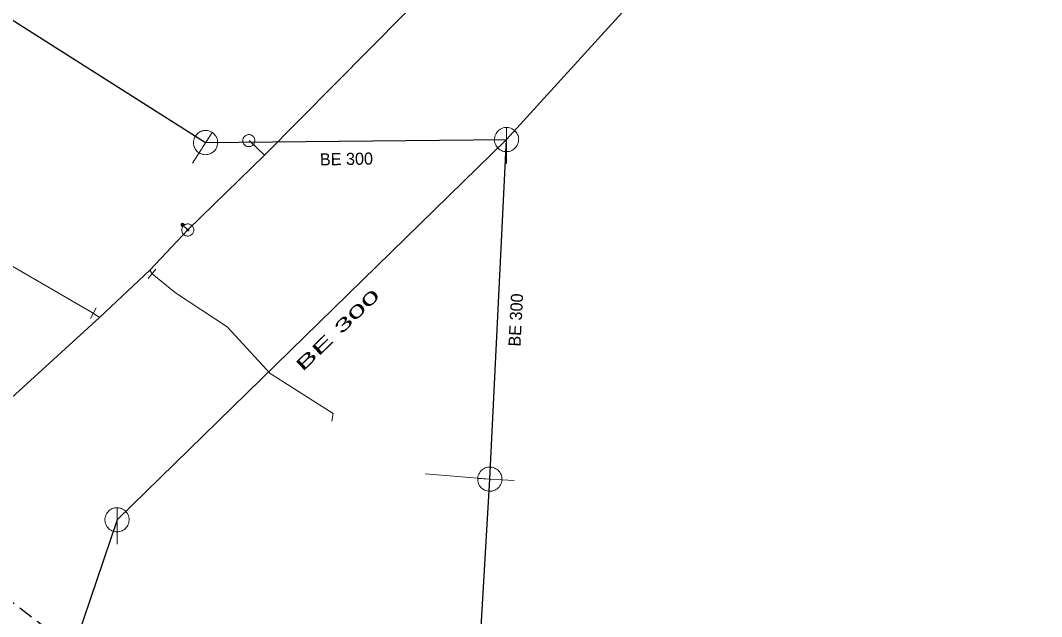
# Model space of a CAD drawing. Extents: x -791337 to -790755, y -988454 to -987923.
# Drawn here: x -791114.4 to -791030.1, y -988240 to -988190.7 of the extents above; entities that cross this region are included whole.
import ezdxf

# ---------------------------------------------------------------- set-up
doc = ezdxf.new("R2010")
doc.units = 0
doc.header["$LTSCALE"] = 0.4
doc.linetypes.add('MEDIUM_DASHED', pattern=[4.5, 3, -1.5])
for name, color, linetype, lineweight in [('1', 7, 'Continuous', 13), ('11', 7, 'Continuous', 13), ('13', 7, 'Continuous', 13), ('14', 7, 'Continuous', 25), ('17', 7, 'Continuous', 25), ('22', 7, 'Continuous', 13), ('23', 7, 'Continuous', 13), ('34', 7, 'Continuous', 13), ('47', 7, 'Continuous', 13), ('63', 7, 'MEDIUM_DASHED', 25), ('9', 7, 'Continuous', 13)]:
    doc.layers.add(name, color=color, linetype=linetype, lineweight=lineweight)

msp = doc.modelspace()

# ---------------------------------------------------------------- linework, layer by layer
at = {"layer": '11'}
msp.add_line((-791080.986, -988228.19), (-791075.638, -988228.634), dxfattribs=at)
at = {"layer": '13'}
for points in [[(-791107.868, -988215.265), (-791108.388, -988214.918), (-791149.015, -988191.33)], [(-791103.529, -988211.659), (-791101.609, -988213.23), (-791097.34, -988216.039), (-791093.789, -988219.899), (-791088.568, -988223.201), (-791088.693, -988223.848)]]:
    msp.add_lwpolyline(points, dxfattribs=at)
at = {"layer": '14'}
for p, q in [((-791137.55, -988176.404), (-791099.119, -988200.823)), ((-791106.431, -988231.991), (-791074.254, -988200.572)), ((-791099.119, -988200.823), (-791074.254, -988200.572)), ((-791106.431, -988231.991), (-791121.225, -988275.947))]:
    msp.add_line(p, q, dxfattribs=at)
at = {"layer": '14', "lineweight": 13}
for p, q in [((-791094.248, -988201.857), (-791095.51, -988200.659)), ((-791100.587, -988208.045), (-791101.018, -988207.619)), ((-791103.719, -988211.362), (-791103.529, -988211.659))]:
    msp.add_line(p, q, dxfattribs=at)
at = {"layer": '14'}
msp.add_lwpolyline([(-791078.328, -988268.275), (-791076.412, -988241.781), (-791075.638, -988228.634), (-791074.254, -988200.572), (-791046.212, -988169.71)], dxfattribs=at)
at = {"layer": '17'}
for points in [[(-791100.587, -988208.045), (-791094.248, -988201.857), (-791082.624, -988190.124), (-791067.283, -988176.118), (-791058.988, -988167.736)], [(-791134.081, -988239.197), (-791107.868, -988215.265), (-791103.719, -988211.362), (-791100.587, -988208.045)]]:
    msp.add_lwpolyline(points, dxfattribs=at)
at = {"layer": '22'}
for p, q in [((-791100.191, -988202.511), (-791098.582, -988199.979)), ((-791074.254, -988202.572), (-791074.253, -988199.572)), ((-791073.639, -988228.732), (-791076.636, -988228.584)), ((-791106.431, -988233.992), (-791106.43, -988230.992))]:
    msp.add_line(p, q, dxfattribs=at)
for points in [[(-791098.275, -988201.359), (-791098.221, -988201.264), (-791098.179, -988201.163), (-791098.147, -988201.058), (-791098.127, -988200.951), (-791098.119, -988200.841), (-791098.123, -988200.732), (-791098.139, -988200.623), (-791098.167, -988200.518), (-791098.206, -988200.415), (-791098.255, -988200.318), (-791098.316, -988200.227), (-791098.387, -988200.142), (-791098.465, -988200.066), (-791098.552, -988200), (-791098.646, -988199.942), (-791098.744, -988199.896), (-791098.848, -988199.86), (-791098.955, -988199.836), (-791099.064, -988199.825), (-791099.173, -988199.824), (-791099.282, -988199.836), (-791099.388, -988199.86), (-791099.493, -988199.896), (-791099.592, -988199.942), (-791099.685, -988199.999), (-791099.772, -988200.066), (-791099.851, -988200.142), (-791099.921, -988200.226), (-791099.981, -988200.318), (-791100.031, -988200.415), (-791100.071, -988200.516), (-791100.098, -988200.622), (-791100.115, -988200.73), (-791100.119, -988200.84), (-791100.111, -988200.95), (-791100.091, -988201.057), (-791100.06, -988201.162), (-791100.017, -988201.263), (-791099.964, -988201.358), (-791099.9, -988201.448), (-791099.827, -988201.529), (-791099.746, -988201.602), (-791099.656, -988201.666), (-791099.561, -988201.72), (-791099.46, -988201.763), (-791099.356, -988201.794), (-791099.248, -988201.814), (-791099.138, -988201.823), (-791099.029, -988201.819), (-791098.921, -988201.803), (-791098.814, -988201.776), (-791098.712, -988201.736), (-791098.615, -988201.687), (-791098.524, -988201.626), (-791098.439, -988201.557), (-791098.363, -988201.477), (-791098.296, -988201.391)], [(-791073.254, -988200.572), (-791073.259, -988200.463), (-791073.277, -988200.355), (-791073.307, -988200.249), (-791073.347, -988200.148), (-791073.399, -988200.051), (-791073.461, -988199.961), (-791073.533, -988199.878), (-791073.613, -988199.804), (-791073.701, -988199.738), (-791073.795, -988199.683), (-791073.895, -988199.638), (-791074, -988199.605), (-791074.107, -988199.583), (-791074.216, -988199.573), (-791074.326, -988199.575), (-791074.434, -988199.589), (-791074.541, -988199.614), (-791074.644, -988199.651), (-791074.742, -988199.7), (-791074.834, -988199.758), (-791074.92, -988199.827), (-791074.997, -988199.904), (-791075.066, -988199.99), (-791075.125, -988200.082), (-791075.173, -988200.18), (-791075.21, -988200.283), (-791075.236, -988200.39), (-791075.25, -988200.498), (-791075.253, -988200.608), (-791075.243, -988200.717), (-791075.222, -988200.824), (-791075.188, -988200.928), (-791075.144, -988201.028), (-791075.089, -988201.123), (-791075.023, -988201.211), (-791074.949, -988201.291), (-791074.866, -988201.363), (-791074.776, -988201.425), (-791074.68, -988201.477), (-791074.578, -988201.518), (-791074.473, -988201.548), (-791074.365, -988201.566), (-791074.255, -988201.572), (-791074.146, -988201.566), (-791074.038, -988201.548), (-791073.933, -988201.519), (-791073.831, -988201.478), (-791073.734, -988201.426), (-791073.644, -988201.364), (-791073.561, -988201.293), (-791073.486, -988201.213), (-791073.421, -988201.125), (-791073.365, -988201.031), (-791073.321, -988200.931), (-791073.287, -988200.827), (-791073.265, -988200.719), (-791073.255, -988200.61)], [(-791075.588, -988227.635), (-791075.697, -988227.635), (-791075.806, -988227.648), (-791075.913, -988227.673), (-791076.016, -988227.708), (-791076.115, -988227.755), (-791076.208, -988227.812), (-791076.295, -988227.88), (-791076.373, -988227.956), (-791076.443, -988228.041), (-791076.502, -988228.132), (-791076.552, -988228.23), (-791076.59, -988228.333), (-791076.618, -988228.439), (-791076.633, -988228.547), (-791076.636, -988228.657), (-791076.628, -988228.766), (-791076.608, -988228.874), (-791076.576, -988228.979), (-791076.532, -988229.079), (-791076.479, -988229.174), (-791076.414, -988229.263), (-791076.341, -988229.344), (-791076.258, -988229.417), (-791076.169, -988229.48), (-791076.074, -988229.533), (-791075.973, -988229.575), (-791075.867, -988229.606), (-791075.76, -988229.626), (-791075.65, -988229.633), (-791075.541, -988229.628), (-791075.433, -988229.613), (-791075.327, -988229.584), (-791075.225, -988229.545), (-791075.128, -988229.495), (-791075.037, -988229.433), (-791074.953, -988229.363), (-791074.877, -988229.284), (-791074.811, -988229.197), (-791074.754, -988229.104), (-791074.708, -988229.004), (-791074.673, -988228.9), (-791074.65, -988228.793), (-791074.638, -988228.684), (-791074.639, -988228.575), (-791074.652, -988228.466), (-791074.675, -988228.36), (-791074.711, -988228.256), (-791074.758, -988228.156), (-791074.816, -988228.063), (-791074.883, -988227.977), (-791074.959, -988227.898), (-791075.044, -988227.829), (-791075.135, -988227.768), (-791075.232, -988227.719), (-791075.335, -988227.68), (-791075.441, -988227.653), (-791075.55, -988227.638)], [(-791105.431, -988231.992), (-791105.436, -988231.883), (-791105.454, -988231.775), (-791105.484, -988231.669), (-791105.524, -988231.568), (-791105.576, -988231.471), (-791105.638, -988231.381), (-791105.71, -988231.298), (-791105.79, -988231.224), (-791105.878, -988231.158), (-791105.972, -988231.103), (-791106.072, -988231.058), (-791106.177, -988231.025), (-791106.284, -988231.003), (-791106.393, -988230.993), (-791106.503, -988230.995), (-791106.611, -988231.009), (-791106.718, -988231.034), (-791106.821, -988231.071), (-791106.919, -988231.12), (-791107.011, -988231.178), (-791107.097, -988231.247), (-791107.174, -988231.324), (-791107.243, -988231.41), (-791107.302, -988231.502), (-791107.35, -988231.6), (-791107.387, -988231.703), (-791107.413, -988231.81), (-791107.427, -988231.918), (-791107.43, -988232.028), (-791107.42, -988232.137), (-791107.399, -988232.244), (-791107.365, -988232.348), (-791107.321, -988232.448), (-791107.266, -988232.543), (-791107.2, -988232.631), (-791107.126, -988232.711), (-791107.043, -988232.783), (-791106.953, -988232.845), (-791106.857, -988232.897), (-791106.755, -988232.938), (-791106.65, -988232.968), (-791106.542, -988232.986), (-791106.432, -988232.992), (-791106.323, -988232.986), (-791106.215, -988232.968), (-791106.11, -988232.939), (-791106.008, -988232.898), (-791105.911, -988232.846), (-791105.821, -988232.784), (-791105.738, -988232.713), (-791105.663, -988232.633), (-791105.598, -988232.545), (-791105.542, -988232.451), (-791105.498, -988232.351), (-791105.464, -988232.247), (-791105.442, -988232.139), (-791105.432, -988232.03)]]:
    msp.add_lwpolyline(points, close=True, dxfattribs=at)
at = {"layer": '23'}
for points in [[(-791095.175, -988200.999), (-791095.141, -988200.959), (-791095.112, -988200.915), (-791095.089, -988200.869), (-791095.069, -988200.821), (-791095.055, -988200.771), (-791095.046, -988200.718), (-791095.043, -988200.666), (-791095.045, -988200.615), (-791095.052, -988200.563), (-791095.065, -988200.512), (-791095.082, -988200.462), (-791095.106, -988200.415), (-791095.133, -988200.371), (-791095.166, -988200.331), (-791095.201, -988200.293), (-791095.243, -988200.259), (-791095.285, -988200.23), (-791095.333, -988200.205), (-791095.379, -988200.186), (-791095.43, -988200.171), (-791095.483, -988200.163), (-791095.535, -988200.159), (-791095.588, -988200.162), (-791095.64, -988200.168), (-791095.689, -988200.181), (-791095.739, -988200.2), (-791095.785, -988200.223), (-791095.83, -988200.251), (-791095.871, -988200.284), (-791095.909, -988200.319), (-791095.942, -988200.359), (-791095.971, -988200.403), (-791095.996, -988200.45), (-791096.016, -988200.498), (-791096.028, -988200.547), (-791096.038, -988200.599), (-791096.042, -988200.652), (-791096.04, -988200.705), (-791096.032, -988200.756)], [(-791095.333, -988200.205), (-791095.379, -988200.186), (-791095.43, -988200.171), (-791095.483, -988200.163), (-791095.535, -988200.159), (-791095.588, -988200.162), (-791095.64, -988200.168), (-791095.689, -988200.181), (-791095.739, -988200.2), (-791095.785, -988200.223), (-791095.83, -988200.251), (-791095.871, -988200.284), (-791095.909, -988200.319), (-791095.942, -988200.359), (-791095.971, -988200.403), (-791095.996, -988200.45), (-791096.016, -988200.498), (-791096.028, -988200.547), (-791096.038, -988200.599), (-791096.042, -988200.652), (-791096.04, -988200.705), (-791096.032, -988200.756), (-791096.02, -988200.806), (-791096.001, -988200.856), (-791095.979, -988200.903), (-791095.95, -988200.947), (-791095.918, -988200.987), (-791095.882, -988201.025), (-791095.842, -988201.058), (-791095.798, -988201.088), (-791095.752, -988201.113), (-791095.703, -988201.132), (-791095.653, -988201.146), (-791095.602, -988201.156), (-791095.549, -988201.158), (-791095.497, -988201.157), (-791095.446, -988201.149), (-791095.394, -988201.137), (-791095.345, -988201.119), (-791095.298, -988201.095)], [(-791096.032, -988200.756), (-791096.02, -988200.806), (-791096.001, -988200.856), (-791095.979, -988200.903), (-791095.95, -988200.947), (-791095.918, -988200.987), (-791095.882, -988201.025), (-791095.842, -988201.058), (-791095.798, -988201.088), (-791095.752, -988201.113), (-791095.703, -988201.132), (-791095.653, -988201.146), (-791095.602, -988201.156), (-791095.549, -988201.158), (-791095.497, -988201.157), (-791095.446, -988201.149), (-791095.394, -988201.137), (-791095.345, -988201.119), (-791095.298, -988201.095), (-791095.254, -988201.067), (-791095.213, -988201.035), (-791095.175, -988200.999), (-791095.141, -988200.959), (-791095.112, -988200.915), (-791095.089, -988200.869), (-791095.069, -988200.821), (-791095.055, -988200.771), (-791095.046, -988200.718), (-791095.043, -988200.666), (-791095.045, -988200.615), (-791095.052, -988200.563), (-791095.065, -988200.512), (-791095.082, -988200.462), (-791095.106, -988200.415), (-791095.133, -988200.371), (-791095.166, -988200.331), (-791095.201, -988200.293), (-791095.243, -988200.259), (-791095.285, -988200.23), (-791095.333, -988200.205)], [(-791095.298, -988201.095), (-791095.254, -988201.067), (-791095.213, -988201.035), (-791095.175, -988200.999)]]:
    msp.add_lwpolyline(points, dxfattribs=at)
at = {"layer": '34'}
for p, q in [((-791103.212, -988211.271), (-791103.845, -988212.045)), ((-791108.14, -988214.483), (-791108.635, -988215.352))]:
    msp.add_line(p, q, dxfattribs=at)
at = {"layer": '47'}
for points in [[(-791100.087, -988208.045), (-791100.09, -988207.993), (-791100.098, -988207.941), (-791100.112, -988207.891), (-791100.13, -988207.842), (-791100.154, -988207.795), (-791100.183, -988207.751), (-791100.216, -988207.711), (-791100.253, -988207.674), (-791100.293, -988207.641), (-791100.337, -988207.612), (-791100.384, -988207.588), (-791100.433, -988207.57), (-791100.483, -988207.556), (-791100.535, -988207.548), (-791100.587, -988207.545), (-791100.639, -988207.548), (-791100.691, -988207.556), (-791100.742, -988207.57), (-791100.79, -988207.588), (-791100.837, -988207.612), (-791100.881, -988207.641), (-791100.922, -988207.674), (-791100.959, -988207.711), (-791100.992, -988207.751), (-791101.02, -988207.795), (-791101.044, -988207.842), (-791101.063, -988207.891), (-791101.076, -988207.941), (-791101.084, -988207.993), (-791101.087, -988208.045), (-791101.084, -988208.097), (-791101.076, -988208.149), (-791101.063, -988208.2), (-791101.044, -988208.248), (-791101.02, -988208.295), (-791100.992, -988208.339), (-791100.959, -988208.38), (-791100.922, -988208.417), (-791100.881, -988208.45), (-791100.837, -988208.478), (-791100.79, -988208.502), (-791100.742, -988208.521), (-791100.691, -988208.534), (-791100.639, -988208.542), (-791100.587, -988208.545), (-791100.535, -988208.542), (-791100.483, -988208.534), (-791100.433, -988208.521), (-791100.384, -988208.502), (-791100.337, -988208.478), (-791100.293, -988208.45), (-791100.253, -988208.417), (-791100.216, -988208.38), (-791100.183, -988208.339), (-791100.154, -988208.295), (-791100.13, -988208.248), (-791100.112, -988208.2), (-791100.098, -988208.149), (-791100.09, -988208.097)], [(-791100.505, -988208.045), (-791100.505, -988208.036), (-791100.507, -988208.028), (-791100.509, -988208.02), (-791100.512, -988208.012), (-791100.516, -988208.004), (-791100.521, -988207.997), (-791100.526, -988207.99), (-791100.532, -988207.984), (-791100.539, -988207.979), (-791100.546, -988207.974), (-791100.554, -988207.97), (-791100.562, -988207.967), (-791100.57, -988207.965), (-791100.578, -988207.963), (-791100.587, -988207.963), (-791100.596, -988207.963), (-791100.604, -988207.965), (-791100.612, -988207.967), (-791100.62, -988207.97), (-791100.628, -988207.974), (-791100.635, -988207.979), (-791100.642, -988207.984), (-791100.648, -988207.99), (-791100.654, -988207.997), (-791100.658, -988208.004), (-791100.662, -988208.012), (-791100.665, -988208.02), (-791100.667, -988208.028), (-791100.669, -988208.036), (-791100.669, -988208.045), (-791100.669, -988208.054), (-791100.667, -988208.062), (-791100.665, -988208.07), (-791100.662, -988208.078), (-791100.658, -988208.086), (-791100.654, -988208.093), (-791100.648, -988208.1), (-791100.642, -988208.106), (-791100.635, -988208.112), (-791100.628, -988208.116), (-791100.62, -988208.12), (-791100.612, -988208.123), (-791100.604, -988208.125), (-791100.596, -988208.127), (-791100.587, -988208.127), (-791100.578, -988208.127), (-791100.57, -988208.125), (-791100.562, -988208.123), (-791100.554, -988208.12), (-791100.546, -988208.116), (-791100.539, -988208.112), (-791100.532, -988208.106), (-791100.526, -988208.1), (-791100.521, -988208.093), (-791100.516, -988208.086), (-791100.512, -988208.078), (-791100.509, -988208.07), (-791100.507, -988208.062), (-791100.505, -988208.054)]]:
    msp.add_lwpolyline(points, close=True, dxfattribs=at)
at = {"layer": '63'}
msp.add_lwpolyline([(-791231.02, -987923.132), (-790755.118, -988202.253), (-790755.118, -988202.253), (-790903.053, -988400.429), (-790903.053, -988400.429), (-791331.504, -988073.857), (-791331.504, -988073.857)], close=True, dxfattribs=at)
at = {"layer": '9'}
for points in [[(-791101.144, -988207.619), (-791101.144, -988207.632), (-791101.142, -988207.645), (-791101.139, -988207.658), (-791101.134, -988207.67), (-791101.128, -988207.682), (-791101.121, -988207.693), (-791101.113, -988207.703), (-791101.103, -988207.713), (-791101.093, -988207.721), (-791101.082, -988207.728), (-791101.07, -988207.734), (-791101.058, -988207.739), (-791101.045, -988207.742), (-791101.032, -988207.744), (-791101.019, -988207.746), (-791101.006, -988207.745), (-791100.993, -988207.743), (-791100.98, -988207.74), (-791100.968, -988207.735), (-791100.956, -988207.729), (-791100.945, -988207.722), (-791100.935, -988207.714), (-791100.925, -988207.704), (-791100.917, -988207.694), (-791100.91, -988207.683), (-791100.904, -988207.671), (-791100.899, -988207.659), (-791100.896, -988207.646), (-791100.894, -988207.633), (-791100.892, -988207.62), (-791100.893, -988207.607), (-791100.895, -988207.594), (-791100.898, -988207.581), (-791100.903, -988207.569), (-791100.909, -988207.557), (-791100.916, -988207.546), (-791100.924, -988207.536), (-791100.934, -988207.526), (-791100.944, -988207.518), (-791100.955, -988207.511), (-791100.967, -988207.505), (-791100.979, -988207.5), (-791100.992, -988207.497), (-791101.005, -988207.495), (-791101.018, -988207.494), (-791101.031, -988207.494), (-791101.044, -988207.496), (-791101.057, -988207.499), (-791101.069, -988207.504), (-791101.081, -988207.51), (-791101.092, -988207.517), (-791101.102, -988207.525), (-791101.112, -988207.535), (-791101.12, -988207.545), (-791101.127, -988207.556), (-791101.133, -988207.568), (-791101.138, -988207.58), (-791101.141, -988207.593), (-791101.143, -988207.606)], [(-791101.124, -988207.619), (-791101.125, -988207.63), (-791101.123, -988207.641), (-791101.12, -988207.652), (-791101.116, -988207.662), (-791101.111, -988207.672), (-791101.105, -988207.681), (-791101.098, -988207.69), (-791101.09, -988207.698), (-791101.081, -988207.705), (-791101.072, -988207.711), (-791101.062, -988207.716), (-791101.052, -988207.72), (-791101.041, -988207.723), (-791101.03, -988207.726), (-791101.019, -988207.726), (-791101.008, -988207.726), (-791100.997, -988207.724), (-791100.986, -988207.721), (-791100.976, -988207.717), (-791100.966, -988207.712), (-791100.957, -988207.706), (-791100.948, -988207.699), (-791100.94, -988207.691), (-791100.933, -988207.682), (-791100.927, -988207.673), (-791100.922, -988207.663), (-791100.918, -988207.653), (-791100.915, -988207.642), (-791100.913, -988207.631), (-791100.912, -988207.62), (-791100.912, -988207.609), (-791100.914, -988207.598), (-791100.917, -988207.587), (-791100.921, -988207.577), (-791100.926, -988207.567), (-791100.932, -988207.558), (-791100.939, -988207.549), (-791100.947, -988207.541), (-791100.956, -988207.534), (-791100.965, -988207.528), (-791100.975, -988207.523), (-791100.985, -988207.519), (-791100.996, -988207.516), (-791101.007, -988207.514), (-791101.018, -988207.514), (-791101.029, -988207.513), (-791101.04, -988207.515), (-791101.051, -988207.518), (-791101.061, -988207.522), (-791101.071, -988207.527), (-791101.08, -988207.533), (-791101.089, -988207.54), (-791101.097, -988207.548), (-791101.104, -988207.557), (-791101.11, -988207.566), (-791101.115, -988207.576), (-791101.119, -988207.586), (-791101.122, -988207.597), (-791101.124, -988207.608)], [(-791101.105, -988207.619), (-791101.105, -988207.628), (-791101.104, -988207.637), (-791101.101, -988207.646), (-791101.098, -988207.654), (-791101.094, -988207.662), (-791101.089, -988207.67), (-791101.083, -988207.677), (-791101.077, -988207.683), (-791101.07, -988207.689), (-791101.062, -988207.694), (-791101.054, -988207.698), (-791101.046, -988207.701), (-791101.037, -988207.704), (-791101.028, -988207.705), (-791101.019, -988207.707), (-791101.01, -988207.706), (-791101.001, -988207.705), (-791100.992, -988207.702), (-791100.984, -988207.699), (-791100.976, -988207.695), (-791100.968, -988207.69), (-791100.961, -988207.684), (-791100.955, -988207.678), (-791100.949, -988207.671), (-791100.944, -988207.663), (-791100.94, -988207.655), (-791100.937, -988207.647), (-791100.934, -988207.638), (-791100.933, -988207.629), (-791100.931, -988207.62), (-791100.932, -988207.611), (-791100.933, -988207.602), (-791100.936, -988207.593), (-791100.939, -988207.585), (-791100.943, -988207.577), (-791100.948, -988207.569), (-791100.954, -988207.562), (-791100.96, -988207.556), (-791100.967, -988207.55), (-791100.975, -988207.545), (-791100.983, -988207.541), (-791100.991, -988207.538), (-791101, -988207.535), (-791101.009, -988207.534), (-791101.018, -988207.533), (-791101.027, -988207.533), (-791101.036, -988207.534), (-791101.045, -988207.537), (-791101.053, -988207.54), (-791101.061, -988207.544), (-791101.069, -988207.549), (-791101.076, -988207.555), (-791101.082, -988207.561), (-791101.088, -988207.568), (-791101.093, -988207.576), (-791101.097, -988207.584), (-791101.1, -988207.592), (-791101.103, -988207.601), (-791101.104, -988207.61)], [(-791101.085, -988207.619), (-791101.085, -988207.626), (-791101.084, -988207.633), (-791101.083, -988207.64), (-791101.08, -988207.646), (-791101.077, -988207.652), (-791101.073, -988207.658), (-791101.069, -988207.664), (-791101.064, -988207.669), (-791101.058, -988207.673), (-791101.052, -988207.677), (-791101.046, -988207.68), (-791101.04, -988207.683), (-791101.033, -988207.684), (-791101.026, -988207.687), (-791101.019, -988207.687), (-791101.012, -988207.687), (-791101.005, -988207.685), (-791100.998, -988207.684), (-791100.992, -988207.681), (-791100.985, -988207.678), (-791100.98, -988207.674), (-791100.974, -988207.67), (-791100.969, -988207.665), (-791100.965, -988207.659), (-791100.961, -988207.653), (-791100.958, -988207.647), (-791100.955, -988207.641), (-791100.953, -988207.634), (-791100.952, -988207.627), (-791100.951, -988207.62), (-791100.951, -988207.613), (-791100.952, -988207.606), (-791100.954, -988207.599), (-791100.957, -988207.593), (-791100.96, -988207.586), (-791100.964, -988207.581), (-791100.968, -988207.575), (-791100.973, -988207.57), (-791100.979, -988207.566), (-791100.984, -988207.562), (-791100.991, -988207.559), (-791100.997, -988207.556), (-791101.004, -988207.554), (-791101.011, -988207.553), (-791101.018, -988207.553), (-791101.025, -988207.553), (-791101.032, -988207.553), (-791101.039, -988207.555), (-791101.045, -988207.558), (-791101.051, -988207.561), (-791101.057, -988207.565), (-791101.063, -988207.569), (-791101.068, -988207.574), (-791101.072, -988207.58), (-791101.076, -988207.585), (-791101.079, -988207.592), (-791101.082, -988207.598), (-791101.083, -988207.605), (-791101.085, -988207.612)], [(-791101.065, -988207.619), (-791101.065, -988207.624), (-791101.065, -988207.629), (-791101.064, -988207.634), (-791101.062, -988207.638), (-791101.06, -988207.643), (-791101.057, -988207.647), (-791101.054, -988207.65), (-791101.05, -988207.654), (-791101.047, -988207.657), (-791101.043, -988207.66), (-791101.038, -988207.662), (-791101.034, -988207.664), (-791101.029, -988207.665), (-791101.024, -988207.667), (-791101.019, -988207.667), (-791101.014, -988207.667), (-791101.009, -988207.666), (-791101.004, -988207.665), (-791101, -988207.663), (-791100.995, -988207.661), (-791100.991, -988207.658), (-791100.987, -988207.655), (-791100.984, -988207.651), (-791100.981, -988207.648), (-791100.978, -988207.644), (-791100.976, -988207.639), (-791100.974, -988207.635), (-791100.973, -988207.63), (-791100.972, -988207.625), (-791100.971, -988207.62), (-791100.971, -988207.615), (-791100.972, -988207.61), (-791100.973, -988207.605), (-791100.975, -988207.601), (-791100.977, -988207.596), (-791100.98, -988207.592), (-791100.983, -988207.588), (-791100.986, -988207.585), (-791100.99, -988207.582), (-791100.994, -988207.579), (-791100.999, -988207.577), (-791101.003, -988207.575), (-791101.008, -988207.574), (-791101.013, -988207.573), (-791101.018, -988207.573), (-791101.023, -988207.573), (-791101.028, -988207.574), (-791101.033, -988207.574), (-791101.037, -988207.576), (-791101.042, -988207.578), (-791101.046, -988207.581), (-791101.049, -988207.584), (-791101.053, -988207.587), (-791101.056, -988207.591), (-791101.059, -988207.595), (-791101.061, -988207.6), (-791101.063, -988207.604), (-791101.064, -988207.609), (-791101.065, -988207.614)], [(-791101.045, -988207.619), (-791101.045, -988207.622), (-791101.046, -988207.625), (-791101.045, -988207.627), (-791101.044, -988207.63), (-791101.043, -988207.633), (-791101.041, -988207.635), (-791101.039, -988207.637), (-791101.037, -988207.639), (-791101.035, -988207.641), (-791101.033, -988207.643), (-791101.03, -988207.645), (-791101.027, -988207.646), (-791101.025, -988207.646), (-791101.022, -988207.647), (-791101.019, -988207.647), (-791101.016, -988207.647), (-791101.013, -988207.647), (-791101.01, -988207.646), (-791101.008, -988207.645), (-791101.005, -988207.644), (-791101.003, -988207.642), (-791101, -988207.64), (-791100.998, -988207.638), (-791100.997, -988207.636), (-791100.995, -988207.634), (-791100.994, -988207.631), (-791100.992, -988207.628), (-791100.992, -988207.626), (-791100.991, -988207.623), (-791100.99, -988207.62), (-791100.991, -988207.617), (-791100.991, -988207.614), (-791100.992, -988207.611), (-791100.993, -988207.609), (-791100.994, -988207.606), (-791100.996, -988207.604), (-791100.997, -988207.601), (-791100.999, -988207.599), (-791101.002, -988207.598), (-791101.004, -988207.596), (-791101.007, -988207.595), (-791101.009, -988207.594), (-791101.012, -988207.593), (-791101.015, -988207.593), (-791101.018, -988207.592), (-791101.021, -988207.593), (-791101.024, -988207.592), (-791101.026, -988207.594), (-791101.029, -988207.594), (-791101.032, -988207.595), (-791101.034, -988207.597), (-791101.036, -988207.598), (-791101.038, -988207.6), (-791101.04, -988207.603), (-791101.042, -988207.605), (-791101.043, -988207.608), (-791101.044, -988207.61), (-791101.045, -988207.613), (-791101.045, -988207.616)], [(-791101.026, -988207.619), (-791101.026, -988207.621), (-791101.026, -988207.621), (-791101.025, -988207.621), (-791101.025, -988207.623), (-791101.026, -988207.624), (-791101.024, -988207.624), (-791101.024, -988207.624), (-791101.024, -988207.626), (-791101.024, -988207.626), (-791101.023, -988207.627), (-791101.021, -988207.627), (-791101.021, -988207.627), (-791101.021, -988207.628), (-791101.019, -988207.628), (-791101.019, -988207.628), (-791101.018, -988207.628), (-791101.017, -988207.628), (-791101.017, -988207.627), (-791101.016, -988207.627), (-791101.014, -988207.627), (-791101.014, -988207.626), (-791101.014, -988207.626), (-791101.013, -988207.625), (-791101.013, -988207.625), (-791101.011, -988207.624), (-791101.011, -988207.623), (-791101.01, -988207.622), (-791101.01, -988207.622), (-791101.01, -988207.621), (-791101.01, -988207.62), (-791101.01, -988207.619), (-791101.01, -988207.618), (-791101.01, -988207.618), (-791101.011, -988207.617), (-791101.011, -988207.616), (-791101.012, -988207.615), (-791101.012, -988207.615), (-791101.013, -988207.614), (-791101.013, -988207.614), (-791101.014, -988207.613), (-791101.015, -988207.613), (-791101.016, -988207.612), (-791101.016, -988207.612), (-791101.017, -988207.612), (-791101.018, -988207.612), (-791101.019, -988207.612), (-791101.02, -988207.612), (-791101.02, -988207.612), (-791101.021, -988207.613), (-791101.022, -988207.612), (-791101.023, -988207.614), (-791101.023, -988207.614), (-791101.024, -988207.614), (-791101.024, -988207.614), (-791101.025, -988207.616), (-791101.025, -988207.617), (-791101.025, -988207.618), (-791101.026, -988207.618), (-791101.026, -988207.619)]]:
    msp.add_lwpolyline(points, close=True, dxfattribs=at)

# ---------------------------------------------------------------- texts
at = {"layer": '1'}
for rotation, p in [(1, (-791089.665, -988202.713)), (87, (-791073.11, -988217.696))]:
    msp.add_text('BE 300', height=1, rotation=rotation, dxfattribs=at).set_placement(p)
at = {"layer": '1', "width": 2.05}
msp.add_text('BE 300', height=1, rotation=44, dxfattribs=at).set_placement((-791091.101, -988219.797))

doc.saveas('drawing.dxf')
